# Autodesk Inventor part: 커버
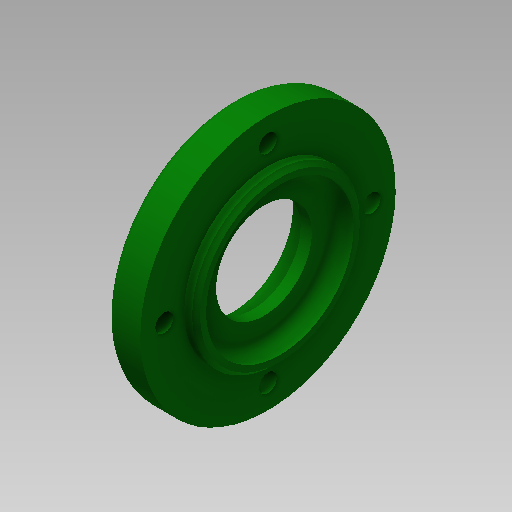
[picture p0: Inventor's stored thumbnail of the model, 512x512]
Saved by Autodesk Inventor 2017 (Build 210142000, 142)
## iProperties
Created: 2019-09
Part Number: 커버
Material: 알루미늄 6061
Document SubType Name: Modeling
Designer: mduedu
Density: 1 g/cm^3
Appearance: 진녹색
Author: mduedu
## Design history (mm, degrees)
sketch "스케치1"
  geometry: C1 r 32 at (0, 0); 1 further point
  constraints: 1 centre point, 1 coincident
  dimensions: "d0" = 64 diameter of C1
extrude "돌출1" new body sketch "스케치1" distance "d1" = 9; taper "d2" = 0 deg
sketch "스케치2"
  geometry: C1 r 21 at (0, 0); 1 further point
  constraints: 1 centre point, 1 coincident
  dimensions: "d3" = 42 diameter of C1
extrude "돌출2" join sketch "스케치2" distance "d4" = 3; taper "d5" = 0 deg
hole "구멍1" diameter "d8" = 24; stored, may be unused: countersink angle "d12" = 90 deg, drill point angle "d14" = 118 deg; dims "d6" = 10, "d7" = 10, "d9" = 6, "d10" = 30, "d11" = 5.2, "d13" = 8
hole "구멍2" diameter "d17" = 37; stored, may be unused: countersink angle "d21" = 90 deg, drill point angle "d23" = 0 deg; dims "d15" = 10, "d16" = 10, "d18" = 6, "d19" = 30, "d20" = 5.2, "d22" = 4
fillet "모깎기1" dims "d24" = 3
fillet "모깎기2" dims "d25" = 3
chamfer "모따기1" distance "d27" = 0.5; stored, may be unused: second distance "d28" = 2, angle "d29" = 30 deg
chamfer "모따기2" distance "d30" = 1; stored, may be unused: second distance "d31" = 2, angle "d32" = 30 deg
sketch "스케치3" dims "d33" = 52
  geometry: 3 further points
  constraints: 2 vertical alignment, 1 coincident, 2 other
hole "구멍3" sketch "스케치3" at (0, 26) diameter "d34" = 4.5; stored, may be unused: countersink angle "d38" = 90 deg, drill point angle "d40" = 0 deg; dims "d35" = 6, "d36" = 8, "d37" = 4.4, "d39" = 4
node "솔리드1"
pattern_circular "원형 패턴1" dims angle "d42" = 360 deg
